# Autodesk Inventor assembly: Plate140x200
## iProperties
Created: 2006-02
Part Number: Plate140x200
Document SubType Name: Assembly
Designer: FranzK
CSToolsMass: 0.3
CSToolsVolume: 275476.0
CSToolsArea: 634.0
Author: FranzK
